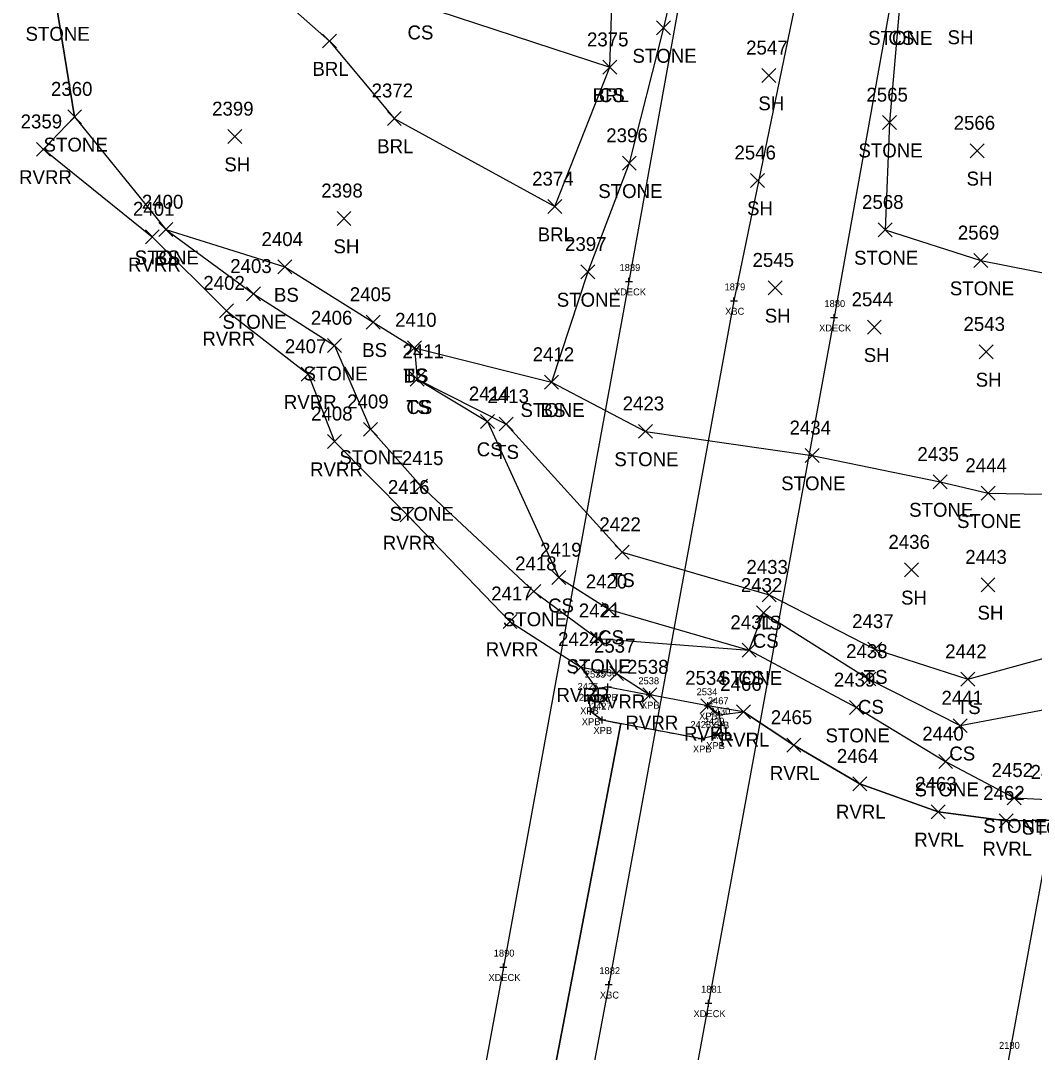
# Model space of a CAD drawing. Extents: x 1472022 to 1479249, y 777216 to 786527.
# Drawn here: x 1473548.5 to 1473693.9, y 779650.8 to 779798.8 of the extents above; entities that cross this region are included whole.
import ezdxf

# ---------------------------------------------------------------- set-up
doc = ezdxf.new("R2010")
doc.units = 0
for name, color, linetype in [('B_A', 7, 'Continuous'), ('B_I', 7, 'Continuous'), ('B_TIC', 7, 'Continuous'), ('BELB', 7, 'Continuous'), ('BSUBM', 7, 'Continuous'), ('L_A', 7, 'Continuous'), ('L_I', 7, 'Continuous'), ('L_TIC', 7, 'Continuous'), ('LABL', 7, 'Continuous'), ('LASF', 7, 'Continuous'), ('LAWE', 7, 'Continuous'), ('LELB', 7, 'Continuous'), ('LSOGP', 7, 'Continuous')]:
    doc.layers.add(name, color=color, linetype=linetype)

msp = doc.modelspace()

# ---------------------------------------------------------------- linework, layer by layer
at = {"layer": 'B_TIC'}
for p, q in [((1473635.72, 779761.4), (1473635.8, 779761.4)), ((1473650.79, 779758.62), (1473650.86, 779758.62)), ((1473665.15, 779756.22), (1473665.23, 779756.22)), ((1473631.02, 779703.04), (1473631.1, 779703.04)), ((1473632.7, 779703.22), (1473632.78, 779703.22)), ((1473638.71, 779702.1), (1473638.78, 779702.1)), ((1473638.71, 779702.1), (1473638.78, 779702.1)), ((1473629.99, 779701.29), (1473630.06, 779701.29)), ((1473629.99, 779701.29), (1473630.06, 779701.29)), ((1473647.05, 779700.52), (1473647.13, 779700.52)), ((1473630.21, 779699.72), (1473630.29, 779699.72)), ((1473648.7, 779699.23), (1473648.78, 779699.23)), ((1473631.89, 779698.47), (1473631.97, 779698.47)), ((1473648.95, 779697.75), (1473649.03, 779697.75)), ((1473646.16, 779695.81), (1473646.24, 779695.81)), ((1473648.08, 779696.29), (1473648.16, 779696.29)), ((1473617.71, 779663.02), (1473617.79, 779663.02)), ((1473632.82, 779660.5), (1473632.89, 779660.5)), ((1473647.14, 779657.83), (1473647.21, 779657.83))]:
    msp.add_line(p, q, dxfattribs=at)
for points in [[(1473635.22, 779761.4), (1473636.22, 779761.4)], [(1473635.72, 779760.9), (1473635.72, 779761.9)], [(1473650.28, 779758.62), (1473651.28, 779758.62)], [(1473650.78, 779758.12), (1473650.78, 779759.12)], [(1473665.15, 779755.72), (1473665.15, 779756.72)], [(1473664.65, 779756.22), (1473665.65, 779756.22)], [(1473630.52, 779703.04), (1473631.52, 779703.04)], [(1473631.02, 779702.54), (1473631.02, 779703.54)], [(1473632.2, 779703.22), (1473633.2, 779703.22)], [(1473632.7, 779702.72), (1473632.7, 779703.72)], [(1473629.98, 779700.79), (1473629.98, 779701.79)], [(1473629.98, 779700.79), (1473629.98, 779701.79)], [(1473638.2, 779702.1), (1473639.2, 779702.1)], [(1473638.2, 779702.1), (1473639.2, 779702.1)], [(1473638.7, 779701.6), (1473638.7, 779702.6)], [(1473638.7, 779701.6), (1473638.7, 779702.6)], [(1473629.48, 779701.29), (1473630.48, 779701.29)], [(1473629.48, 779701.29), (1473630.48, 779701.29)], [(1473630.21, 779699.22), (1473630.21, 779700.22)], [(1473646.55, 779700.52), (1473647.55, 779700.52)], [(1473647.05, 779700.02), (1473647.05, 779701.02)], [(1473629.71, 779699.72), (1473630.71, 779699.72)], [(1473631.89, 779697.97), (1473631.89, 779698.97)], [(1473648.2, 779699.23), (1473649.2, 779699.23)], [(1473648.7, 779698.73), (1473648.7, 779699.73)], [(1473631.39, 779698.47), (1473632.39, 779698.47)], [(1473648.45, 779697.75), (1473649.45, 779697.75)], [(1473648.95, 779697.25), (1473648.95, 779698.25)], [(1473645.66, 779695.81), (1473646.66, 779695.81)], [(1473646.16, 779695.31), (1473646.16, 779696.31)], [(1473647.58, 779696.29), (1473648.58, 779696.29)], [(1473648.08, 779695.79), (1473648.08, 779696.79)], [(1473617.21, 779663.02), (1473618.21, 779663.02)], [(1473617.71, 779662.52), (1473617.71, 779663.52)], [(1473632.31, 779660.5), (1473633.31, 779660.5)], [(1473632.81, 779660), (1473632.81, 779661)], [(1473646.63, 779657.83), (1473647.63, 779657.83)], [(1473647.13, 779657.33), (1473647.13, 779658.33)]]:
    msp.add_lwpolyline(points, dxfattribs=at)
at = {"layer": 'BELB'}
for points in [[(1473646.9, 779823.47), (1473635.72, 779761.4), (1473617.71, 779663.02), (1473604.51, 779591.79), (1473588.93, 779505.83), (1473570.78, 779407.46), (1473559.55, 779345.54)], [(1473663.54, 779820.45), (1473650.78, 779758.62), (1473632.81, 779660.5), (1473616.07, 779571.01), (1473603.54, 779503.11), (1473585.53, 779404.85), (1473573.79, 779342.6)], [(1473676.24, 779818.18), (1473665.15, 779756.22), (1473647.13, 779657.83), (1473630.64, 779568.27), (1473618.22, 779500.38), (1473600.13, 779402.08), (1473588.74, 779339.91)], [(1473632.64, 779331.64), (1473643.77, 779393.67), (1473661.77, 779492.35), (1473674.97, 779565.3), (1473690.2, 779649.78), (1473708.22, 779748.21)]]:
    msp.add_lwpolyline(points, dxfattribs=at)
at = {"layer": 'BSUBM'}
for points in [[(1473629.98, 779701.29), (1473631.02, 779703.04), (1473632.7, 779703.22), (1473638.7, 779702.1)], [(1473629.98, 779701.29), (1473630.21, 779699.72), (1473631.89, 779698.47), (1473646.16, 779695.81), (1473648.08, 779696.29), (1473648.95, 779697.75), (1473648.7, 779699.23), (1473647.05, 779700.52), (1473638.7, 779702.1)]]:
    msp.add_lwpolyline(points, dxfattribs=at)
at = {"layer": 'L_TIC'}
for points in [[(1473639.68, 779796.78), (1473641.68, 779798.78)], [(1473641.68, 779796.78), (1473639.68, 779798.78)], [(1473591.77, 779794.9), (1473593.77, 779796.9)], [(1473593.77, 779794.9), (1473591.77, 779796.9)], [(1473631.96, 779791.13), (1473633.96, 779793.13)], [(1473633.96, 779791.13), (1473631.96, 779793.13)], [(1473631.96, 779791.13), (1473633.96, 779793.13)], [(1473633.96, 779791.13), (1473631.96, 779793.13)], [(1473654.79, 779789.96), (1473656.79, 779791.96)], [(1473656.79, 779789.96), (1473654.79, 779791.96)], [(1473555.2, 779784.03), (1473557.2, 779786.03)], [(1473557.2, 779784.03), (1473555.2, 779786.03)], [(1473555.2, 779784.03), (1473557.2, 779786.03)], [(1473557.2, 779784.03), (1473555.2, 779786.03)], [(1473601.06, 779783.8), (1473603.06, 779785.8)], [(1473603.06, 779783.8), (1473601.06, 779785.8)], [(1473672.09, 779783.2), (1473674.09, 779785.2)], [(1473674.09, 779783.2), (1473672.09, 779785.2)], [(1473578.19, 779781.19), (1473580.19, 779783.19)], [(1473580.19, 779781.19), (1473578.19, 779783.19)], [(1473550.72, 779779.36), (1473552.72, 779781.36)], [(1473552.72, 779779.36), (1473550.72, 779781.36)], [(1473684.66, 779779.16), (1473686.66, 779781.16)], [(1473686.66, 779779.16), (1473684.66, 779781.16)], [(1473634.77, 779777.37), (1473636.77, 779779.37)], [(1473636.77, 779777.37), (1473634.77, 779779.37)], [(1473653.17, 779774.9), (1473655.17, 779776.9)], [(1473655.17, 779774.9), (1473653.17, 779776.9)], [(1473624.09, 779771.15), (1473626.09, 779773.15)], [(1473626.09, 779771.15), (1473624.09, 779773.15)], [(1473593.84, 779769.44), (1473595.84, 779771.44)], [(1473595.84, 779769.44), (1473593.84, 779771.44)], [(1473568.27, 779767.84), (1473570.27, 779769.84)], [(1473570.27, 779767.84), (1473568.27, 779769.84)], [(1473568.27, 779767.84), (1473570.27, 779769.84)], [(1473570.27, 779767.84), (1473568.27, 779769.84)], [(1473671.47, 779767.8), (1473673.47, 779769.8)], [(1473673.47, 779767.8), (1473671.47, 779769.8)], [(1473566.34, 779766.82), (1473568.34, 779768.82)], [(1473568.34, 779766.82), (1473566.34, 779768.82)], [(1473685.21, 779763.41), (1473687.21, 779765.41)], [(1473687.21, 779763.41), (1473685.21, 779765.41)], [(1473585.35, 779762.48), (1473587.35, 779764.48)], [(1473587.35, 779762.48), (1473585.35, 779764.48)], [(1473628.81, 779761.77), (1473630.81, 779763.77)], [(1473630.81, 779761.77), (1473628.81, 779763.77)], [(1473655.71, 779759.49), (1473657.71, 779761.49)], [(1473657.71, 779759.49), (1473655.71, 779761.49)], [(1473580.85, 779758.61), (1473582.85, 779760.61)], [(1473582.85, 779758.61), (1473580.85, 779760.61)], [(1473577, 779756.19), (1473579, 779758.19)], [(1473579, 779756.19), (1473577, 779758.19)], [(1473598.01, 779754.56), (1473600.01, 779756.56)], [(1473600.01, 779754.56), (1473598.01, 779756.56)], [(1473669.92, 779753.84), (1473671.92, 779755.84)], [(1473671.92, 779753.84), (1473669.92, 779755.84)], [(1473592.48, 779751.19), (1473594.48, 779753.19)], [(1473594.48, 779751.19), (1473592.48, 779753.19)], [(1473603.95, 779750.89), (1473605.95, 779752.89)], [(1473605.95, 779750.89), (1473603.95, 779752.89)], [(1473603.95, 779750.89), (1473605.95, 779752.89)], [(1473605.95, 779750.89), (1473603.95, 779752.89)], [(1473685.97, 779750.3), (1473687.97, 779752.3)], [(1473687.97, 779750.3), (1473685.97, 779752.3)], [(1473588.7, 779747.1), (1473590.7, 779749.1)], [(1473590.7, 779747.1), (1473588.7, 779749.1)], [(1473604.35, 779746.38), (1473606.35, 779748.38)], [(1473606.35, 779746.38), (1473604.35, 779748.38)], [(1473604.35, 779746.38), (1473606.35, 779748.38)], [(1473606.35, 779746.38), (1473604.35, 779748.38)], [(1473623.6, 779745.95), (1473625.6, 779747.95)], [(1473625.6, 779745.95), (1473623.6, 779747.95)], [(1473623.6, 779745.95), (1473625.6, 779747.95)], [(1473625.6, 779745.95), (1473623.6, 779747.95)], [(1473614.44, 779740.31), (1473616.44, 779742.31)], [(1473616.44, 779740.31), (1473614.44, 779742.31)], [(1473617.12, 779739.94), (1473619.12, 779741.94)], [(1473619.12, 779739.94), (1473617.12, 779741.94)], [(1473597.64, 779739.18), (1473599.64, 779741.18)], [(1473599.64, 779739.18), (1473597.64, 779741.18)], [(1473637.08, 779738.89), (1473639.08, 779740.89)], [(1473639.08, 779738.89), (1473637.08, 779740.89)], [(1473592.46, 779737.44), (1473594.46, 779739.44)], [(1473594.46, 779737.44), (1473592.46, 779739.44)], [(1473661.02, 779735.43), (1473663.02, 779737.43)], [(1473663.02, 779735.43), (1473661.02, 779737.43)], [(1473604.84, 779731.05), (1473606.84, 779733.05)], [(1473606.84, 779731.05), (1473604.84, 779733.05)], [(1473679.36, 779731.63), (1473681.36, 779733.63)], [(1473681.36, 779731.63), (1473679.36, 779733.63)], [(1473686.24, 779730.02), (1473688.24, 779732.02)], [(1473688.24, 779730.02), (1473686.24, 779732.02)], [(1473602.89, 779726.9), (1473604.89, 779728.9)], [(1473604.89, 779726.9), (1473602.89, 779728.9)], [(1473633.73, 779721.55), (1473635.73, 779723.55)], [(1473635.73, 779721.55), (1473633.73, 779723.55)], [(1473675.26, 779719.03), (1473677.26, 779721.03)], [(1473677.26, 779719.03), (1473675.26, 779721.03)], [(1473624.67, 779717.9), (1473626.67, 779719.9)], [(1473626.67, 779717.9), (1473624.67, 779719.9)], [(1473621.09, 779715.93), (1473623.09, 779717.93)], [(1473623.09, 779715.93), (1473621.09, 779717.93)], [(1473686.23, 779716.87), (1473688.23, 779718.87)], [(1473688.23, 779716.87), (1473686.23, 779718.87)], [(1473654.83, 779715.43), (1473656.83, 779717.43)], [(1473656.83, 779715.43), (1473654.83, 779717.43)], [(1473631.86, 779713.34), (1473633.86, 779715.34)], [(1473633.86, 779713.34), (1473631.86, 779715.34)], [(1473654.04, 779712.83), (1473656.04, 779714.83)], [(1473656.04, 779712.83), (1473654.04, 779714.83)], [(1473617.65, 779711.62), (1473619.65, 779713.62)], [(1473619.65, 779711.62), (1473617.65, 779713.62)], [(1473630.22, 779709.18), (1473632.22, 779711.18)], [(1473632.22, 779709.18), (1473630.22, 779711.18)], [(1473651.96, 779707.5), (1473653.96, 779709.5)], [(1473653.96, 779707.5), (1473651.96, 779709.5)], [(1473651.96, 779707.5), (1473653.96, 779709.5)], [(1473653.96, 779707.5), (1473651.96, 779709.5)], [(1473670, 779707.65), (1473672, 779709.65)], [(1473672, 779707.65), (1473670, 779709.65)], [(1473627.81, 779705.07), (1473629.81, 779707.07)], [(1473629.81, 779705.07), (1473627.81, 779707.07)], [(1473632.96, 779704.13), (1473634.96, 779706.13)], [(1473634.96, 779704.13), (1473632.96, 779706.13)], [(1473669.13, 779703.35), (1473671.13, 779705.35)], [(1473671.13, 779703.35), (1473669.13, 779705.35)], [(1473683.35, 779703.32), (1473685.35, 779705.32)], [(1473685.35, 779703.32), (1473683.35, 779705.32)], [(1473637.7, 779701.1), (1473639.7, 779703.1)], [(1473639.7, 779701.1), (1473637.7, 779703.1)], [(1473646.05, 779699.52), (1473648.05, 779701.52)], [(1473648.05, 779699.52), (1473646.05, 779701.52)], [(1473651.17, 779698.65), (1473653.17, 779700.65)], [(1473653.17, 779698.65), (1473651.17, 779700.65)], [(1473667.38, 779699.26), (1473669.38, 779701.26)], [(1473669.38, 779699.26), (1473667.38, 779701.26)], [(1473682.24, 779696.66), (1473684.24, 779698.66)], [(1473684.24, 779696.66), (1473682.24, 779698.66)], [(1473658.37, 779693.87), (1473660.37, 779695.87)], [(1473660.37, 779693.87), (1473658.37, 779695.87)], [(1473680.15, 779691.51), (1473682.15, 779693.51)], [(1473682.15, 779691.51), (1473680.15, 779693.51)], [(1473667.84, 779688.31), (1473669.84, 779690.31)], [(1473669.84, 779688.31), (1473667.84, 779690.31)], [(1473690, 779686.28), (1473692, 779688.28)], [(1473692, 779686.28), (1473690, 779688.28)], [(1473679.09, 779684.3), (1473681.09, 779686.3)], [(1473681.09, 779684.3), (1473679.09, 779686.3)], [(1473688.85, 779683), (1473690.85, 779685)], [(1473690.85, 779683), (1473688.85, 779685)]]:
    msp.add_lwpolyline(points, dxfattribs=at)
at = {"layer": 'LABL'}
msp.add_lwpolyline([(1473563.02, 779816.95), (1473573.62, 779812.81), (1473592.77, 779795.9), (1473602.06, 779784.8), (1473625.09, 779772.15), (1473632.96, 779792.13), (1473633.46, 779807.01), (1473632.38, 779820.76), (1473631.38, 779834.48), (1473631.97, 779850.31)], dxfattribs=at)
at = {"layer": 'LASF'}
for points in [[(1473556.2, 779785.03), (1473553.61, 779800.93), (1473563.02, 779816.95), (1473561.4, 779839.67), (1473556.93, 779858.57)], [(1473645.76, 779818.01), (1473644.27, 779813.32), (1473640.68, 779797.78), (1473635.77, 779778.37), (1473629.81, 779762.77), (1473624.6, 779746.95), (1473638.08, 779739.89), (1473662.02, 779736.43), (1473680.36, 779732.63), (1473687.24, 779731.02), (1473707.97, 779730.64), (1473726.96, 779732.5), (1473741.69, 779728.71)], [(1473674.63, 779812.66), (1473674.49, 779800.35), (1473673.09, 779784.2), (1473672.47, 779768.8), (1473686.21, 779764.41), (1473701.45, 779761.38), (1473708.8, 779772.85), (1473712.08, 779786.76), (1473716.54, 779806.01), (1473719.24, 779801.78), (1473727.32, 779798.69), (1473745.52, 779794.84), (1473745.88, 779788.84), (1473745.17, 779774.32), (1473743.47, 779755.08), (1473741.69, 779728.71)], [(1473556.2, 779785.03), (1473569.27, 779768.84), (1473581.85, 779759.61), (1473593.48, 779752.19), (1473598.64, 779740.18), (1473605.84, 779732.05), (1473622.09, 779716.93), (1473631.22, 779710.18), (1473652.96, 779708.5), (1473668.38, 779700.26), (1473681.15, 779692.51), (1473691, 779687.28), (1473696.6, 779687.02), (1473702.71, 779688.1)]]:
    msp.add_lwpolyline(points, dxfattribs=at)
at = {"layer": 'LAWE'}
for points in [[(1473551.72, 779780.36), (1473567.34, 779767.82), (1473578, 779757.19), (1473589.7, 779748.1), (1473593.46, 779738.44), (1473603.89, 779727.9), (1473618.65, 779712.62), (1473628.81, 779706.07), (1473633.96, 779705.13), (1473638.7, 779702.1)], [(1473702.76, 779686.97), (1473697.52, 779684.1), (1473689.85, 779684), (1473680.09, 779685.3), (1473668.84, 779689.31), (1473659.37, 779694.87), (1473652.17, 779699.65), (1473647.05, 779700.52)]]:
    msp.add_lwpolyline(points, dxfattribs=at)
at = {"layer": 'LELB'}
for points in [[(1473573.62, 779812.81), (1473580.9, 779829.15), (1473579.92, 779858.13), (1473599.66, 779855.69), (1473599.53, 779833.14), (1473600.61, 779811.49), (1473605.51, 779801.13), (1473632.96, 779792.13)], [(1473569.27, 779768.84), (1473586.35, 779763.48), (1473599.01, 779755.56), (1473604.95, 779751.89), (1473624.6, 779746.95)], [(1473604.95, 779751.89), (1473605.35, 779747.38), (1473618.12, 779740.94), (1473634.73, 779722.55), (1473655.83, 779716.43), (1473671, 779708.65), (1473684.35, 779704.32), (1473697.38, 779707.91), (1473706.94, 779710.72), (1473712.92, 779706.56)], [(1473605.35, 779747.38), (1473615.44, 779741.31), (1473625.67, 779718.9), (1473632.86, 779714.34), (1473652.96, 779708.5), (1473655.04, 779713.83), (1473670.13, 779704.35), (1473683.24, 779697.66), (1473698.13, 779700.52), (1473706.67, 779705.76), (1473709.93, 779702.26)]]:
    msp.add_lwpolyline(points, dxfattribs=at)
at = {"layer": 'LSOGP'}
for points in [[(1473553.61, 779800.93), (1473556.2, 779785.03), (1473551.72, 779780.36), (1473567.34, 779767.82), (1473578, 779757.19), (1473589.7, 779748.1), (1473593.46, 779738.44), (1473603.89, 779727.9), (1473618.65, 779712.62), (1473628.81, 779706.07), (1473631.02, 779703.04), (1473630.5, 779702.17), (1473629.98, 779701.29), (1473630.1, 779700.51), (1473630.21, 779699.72), (1473631.05, 779699.09), (1473631.89, 779698.47), (1473632.78, 779698.3), (1473633.67, 779698.13), (1473634.56, 779697.97), (1473590.42, 779467.25)], [(1473590.42, 779467.25), (1473634.56, 779697.97), (1473635.46, 779697.8), (1473636.35, 779697.64), (1473637.24, 779697.47), (1473638.13, 779697.3), (1473639.02, 779697.14), (1473639.92, 779696.97), (1473640.81, 779696.81), (1473641.7, 779696.64), (1473642.59, 779696.47), (1473643.48, 779696.31), (1473644.38, 779696.14), (1473645.27, 779695.98), (1473646.16, 779695.81), (1473647.12, 779696.05), (1473648.08, 779696.29), (1473648.51, 779697.02), (1473648.95, 779697.75), (1473648.82, 779698.49), (1473648.7, 779699.23), (1473652.17, 779699.65), (1473659.37, 779694.87), (1473668.84, 779689.31), (1473680.09, 779685.3), (1473689.85, 779684), (1473697.52, 779684.1)]]:
    msp.add_lwpolyline(points, dxfattribs=at)

# ---------------------------------------------------------------- texts
at = {"layer": 'B_A'}
for s, p in [('XDECK', (1473633.56, 779759.4)), ('XBC', (1473649.52, 779756.62)), ('XDECK', (1473662.99, 779754.22)), ('XPB', (1473629.75, 779701.04)), ('XPB', (1473631.43, 779701.22)), ('XPB', (1473628.72, 779699.29)), ('XPB', (1473628.72, 779699.29)), ('XPB', (1473637.44, 779700.1)), ('XPB', (1473637.44, 779700.1)), ('XPB', (1473628.95, 779697.72)), ('XPB', (1473645.78, 779698.52)), ('XPB', (1473630.63, 779696.47)), ('XPB', (1473647.43, 779697.23)), ('XPB', (1473647.69, 779695.75)), ('XPB', (1473644.9, 779693.81)), ('XPB', (1473646.81, 779694.29)), ('XDECK', (1473615.55, 779661.02)), ('XBC', (1473631.55, 779658.5)), ('XDECK', (1473644.98, 779655.83))]:
    msp.add_text(s, height=1, dxfattribs=at).set_placement(p)
at = {"layer": 'B_I'}
for s, p in [('1889', (1473634.37, 779762.9)), ('1879', (1473649.43, 779760.12)), ('1880', (1473663.76, 779757.72)), ('2535', (1473629.39, 779704.54)), ('2536', (1473631.04, 779704.72)), ('2538', (1473637.07, 779703.6)), ('2538', (1473637.07, 779703.6)), ('2425', (1473628.35, 779702.79)), ('2425', (1473628.35, 779702.79)), ('2534', (1473645.42, 779702.02)), ('2426', (1473628.55, 779701.22)), ('2467', (1473647.04, 779700.73)), ('2427', (1473630.26, 779699.97)), ('2430', (1473647.28, 779699.25)), ('2429', (1473646.44, 779697.79)), ('2428', (1473644.53, 779697.31)), ('1890', (1473616.32, 779664.52)), ('1882', (1473631.47, 779662)), ('1881', (1473646.07, 779659.33)), ('2180', (1473688.81, 779651.28))]:
    msp.add_text(s, height=1, dxfattribs=at).set_placement(p)
at = {"layer": 'L_A'}
for s, p in [('STONE', (1473549.15, 779795.93)), ('CS', (1473603.95, 779796.13)), ('STONE', (1473670.03, 779795.35)), ('CS', (1473672.93, 779795.35)), ('SH', (1473681.43, 779795.44)), ('STONE', (1473636.22, 779792.78)), ('BRL', (1473590.31, 779790.9)), ('BRL', (1473630.5, 779787.13)), ('CS', (1473631.4, 779787.13)), ('SH', (1473654.28, 779785.96)), ('STONE', (1473551.74, 779780.03)), ('STONE', (1473551.74, 779780.03)), ('BRL', (1473599.6, 779779.8)), ('STONE', (1473668.64, 779779.2)), ('SH', (1473577.67, 779777.19)), ('RVRR', (1473548.23, 779775.36)), ('SH', (1473684.15, 779775.16)), ('STONE', (1473631.32, 779773.37)), ('SH', (1473652.66, 779770.9)), ('BRL', (1473622.63, 779767.15)), ('SH', (1473593.33, 779765.44)), ('STONE', (1473564.81, 779763.84)), ('BS', (1473567.71, 779763.84)), ('STONE', (1473668.01, 779763.8)), ('RVRR', (1473563.85, 779762.82)), ('STONE', (1473681.75, 779759.41)), ('BS', (1473584.79, 779758.48)), ('STONE', (1473625.36, 779757.77)), ('STONE', (1473577.4, 779754.61)), ('SH', (1473655.2, 779755.49)), ('RVRR', (1473574.52, 779752.19)), ('BS', (1473597.45, 779750.56)), ('SH', (1473669.4, 779749.84)), ('STONE', (1473589.02, 779747.19)), ('TS', (1473603.36, 779746.89)), ('BS', (1473603.39, 779746.89)), ('SH', (1473685.46, 779746.3)), ('RVRR', (1473586.21, 779743.1)), ('TS', (1473603.76, 779742.38)), ('CS', (1473603.79, 779742.38)), ('STONE', (1473620.15, 779741.95)), ('BS', (1473623.04, 779741.95)), ('STONE', (1473594.18, 779735.18)), ('CS', (1473613.88, 779736.31)), ('TS', (1473616.53, 779735.94)), ('STONE', (1473633.62, 779734.89)), ('RVRR', (1473589.97, 779733.44)), ('STONE', (1473657.56, 779731.43)), ('STONE', (1473675.91, 779727.63)), ('STONE', (1473601.38, 779727.05)), ('STONE', (1473682.78, 779726.02)), ('RVRR', (1473600.4, 779722.9)), ('TS', (1473633.13, 779717.55)), ('SH', (1473674.75, 779715.03)), ('CS', (1473624.11, 779713.9)), ('SH', (1473685.72, 779712.87)), ('STONE', (1473617.63, 779711.93)), ('TS', (1473654.23, 779711.43)), ('CS', (1473631.3, 779709.34)), ('CS', (1473653.48, 779708.83)), ('RVRR', (1473615.17, 779707.62)), ('STONE', (1473626.76, 779705.18)), ('STONE', (1473648.5, 779703.5)), ('CS', (1473651.4, 779703.5)), ('TS', (1473669.4, 779703.65)), ('RVRR', (1473625.32, 779701.07)), ('RVRR', (1473630.48, 779700.13)), ('CS', (1473668.57, 779699.35)), ('TS', (1473682.76, 779699.32)), ('RVRR', (1473635.22, 779697.1)), ('RVRL', (1473643.62, 779695.52)), ('STONE', (1473663.92, 779695.26)), ('RVRL', (1473648.74, 779694.65)), ('CS', (1473681.68, 779692.66)), ('RVRL', (1473655.93, 779689.87)), ('STONE', (1473676.69, 779687.51)), ('RVRL', (1473665.41, 779684.31)), ('STONE', (1473686.54, 779682.28)), ('STONE', (1473692.14, 779682.02)), ('RVRL', (1473676.65, 779680.3)), ('RVRL', (1473686.42, 779679))]:
    msp.add_text(s, height=2, dxfattribs=at).set_placement(p)
at = {"layer": 'L_I'}
for s, p in [('2375', (1473629.7, 779795.13)), ('2375', (1473629.7, 779795.13)), ('2547', (1473652.53, 779793.96)), ('2360', (1473552.8, 779788.03)), ('2360', (1473552.8, 779788.03)), ('2372', (1473598.8, 779787.8)), ('2565', (1473669.79, 779787.2)), ('2399', (1473575.92, 779785.19)), ('2359', (1473548.45, 779783.36)), ('2566', (1473682.3, 779783.16)), ('2396', (1473632.46, 779781.37)), ('2546', (1473650.85, 779778.9)), ('2374', (1473621.83, 779775.15)), ('2398', (1473591.58, 779773.44)), ('2401', (1473564.57, 779770.82)), ('2400', (1473565.84, 779771.84)), ('2400', (1473565.84, 779771.84)), ('2568', (1473669.16, 779771.8)), ('2404', (1473583.01, 779766.48)), ('2569', (1473682.9, 779767.41)), ('2397', (1473626.55, 779765.77)), ('2545', (1473653.45, 779763.49)), ('2403', (1473578.52, 779762.61)), ('2402', (1473574.66, 779760.19)), ('2405', (1473595.67, 779758.56)), ('2544', (1473667.66, 779757.84)), ('2406', (1473590.09, 779755.19)), ('2410', (1473602.17, 779754.89)), ('2410', (1473602.17, 779754.89)), ('2543', (1473683.71, 779754.3)), ('2407', (1473586.36, 779751.1)), ('2411', (1473603.23, 779750.38)), ('2411', (1473603.23, 779750.38)), ('2412', (1473621.91, 779749.95)), ('2412', (1473621.91, 779749.95)), ('2414', (1473612.75, 779744.31)), ('2413', (1473615.43, 779743.94)), ('2409', (1473595.29, 779743.18)), ('2423', (1473634.82, 779742.89)), ('2408', (1473590.12, 779741.44)), ('2434', (1473658.76, 779739.43)), ('2415', (1473603.15, 779735.05)), ('2435', (1473677.1, 779735.63)), ('2444', (1473683.98, 779734.02)), ('2416', (1473601.14, 779730.9)), ('2422', (1473631.47, 779725.55)), ('2419', (1473622.97, 779721.9)), ('2436', (1473672.94, 779723.03)), ('2443', (1473683.97, 779720.87)), ('2418', (1473619.39, 779719.93)), ('2433', (1473652.57, 779719.43)), ('2420', (1473629.52, 779717.34)), ('2432', (1473651.78, 779716.83)), ('2417', (1473615.96, 779715.62)), ('2421', (1473628.52, 779713.18)), ('2431', (1473650.27, 779711.5)), ('2431', (1473650.27, 779711.5)), ('2437', (1473667.74, 779711.65)), ('2424', (1473625.55, 779709.07)), ('2537', (1473630.7, 779708.13)), ('2438', (1473666.87, 779707.35)), ('2442', (1473681.09, 779707.32)), ('2538', (1473635.44, 779705.1)), ('2534', (1473643.79, 779703.52)), ('2466', (1473648.81, 779702.65)), ('2439', (1473665.11, 779703.26)), ('2441', (1473680.55, 779700.66)), ('2465', (1473656.06, 779697.87)), ('2440', (1473677.8, 779695.51)), ('2464', (1473665.54, 779692.31)), ('2452', (1473687.74, 779690.28)), ('2453', (1473693.34, 779690.02)), ('2463', (1473676.78, 779688.3)), ('2462', (1473686.54, 779687))]:
    msp.add_text(s, height=2, dxfattribs=at).set_placement(p)

doc.saveas('drawing.dxf')
